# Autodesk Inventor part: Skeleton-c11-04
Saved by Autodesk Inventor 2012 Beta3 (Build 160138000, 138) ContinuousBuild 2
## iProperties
Created: 2011-01
Part Number: Skeleton-c11-04
Material: Default
Document SubType Name: Modeling
Designer: Beta-8540w
Density: 1 g/cm^3
_SkeletonDoc: Frame Skeleton File
_Version: 15.0.0
Author: Beta-8540w
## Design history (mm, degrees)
sketch "Reference Skeleton"
  geometry: L1 through (404.523, 1164.395) direction (1, 0); L2 through (325.691, 1070.446) direction (1, 0); 34 other entities
  constraints: 10 horizontal
